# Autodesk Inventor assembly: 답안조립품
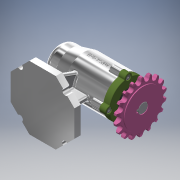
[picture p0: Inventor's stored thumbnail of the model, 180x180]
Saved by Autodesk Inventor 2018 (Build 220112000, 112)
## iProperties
Created: 2021-01
Part Number: 답안조립품
Material: 일반
Document SubType Name: Assembly
Designer: home
Author: home
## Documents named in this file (12)
- C:\Users\home\Desktop\710106V1039\답안조립품.iam
- C:\Users\home\Desktop\710106V1039\본체.ipt
- C:\Users\home\Desktop\710106V1039\축.ipt
- C:\Users\home\Desktop\710106V1039\베어링 6004.ipt
- C:\Users\home\Desktop\710106V1039\어댑터슬리브.ipt
- C:\Users\home\Desktop\710106V1039\커버.ipt
- C:\Users\home\Desktop\710106V1039\오일 실.ipt
- C:\Users\home\Desktop\710106V1039\키 5 x 5 x 14.ipt
- C:\Users\home\Desktop\710106V1039\볼트 M4.ipt
- C:\Users\home\Desktop\710106V1039\베어링 51202.ipt
- C:\Users\home\Desktop\710106V1039\스프로킷.ipt
- C:\Users\home\Desktop\710106V1039\멈춤나사 M3.ipt
